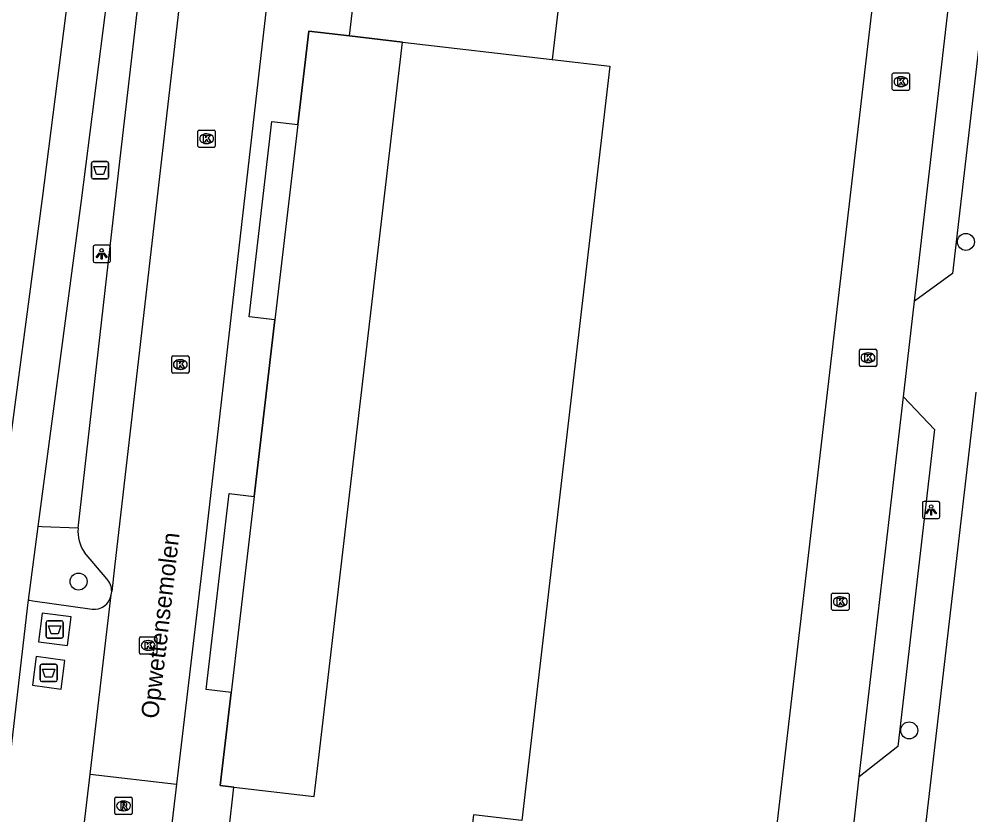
# Model space of a CAD drawing. Extents: x 161243 to 161752, y 384138 to 384885.
# Drawn here: x 161298.5 to 161353.3, y 384518.6 to 384564.5 of the extents above; entities that cross this region are included whole.
import ezdxf

# ---------------------------------------------------------------- set-up
doc = ezdxf.new("R2010")
doc.units = 0
for name, color, linetype in [('IMGEO_Afval_apart_plaats', 7, 'Continuous'), ('IMGEO_Afvalbak', 7, 'Continuous'), ('IMGEO_Berm_groen', 7, 'Continuous'), ('IMGEO_Boom', 7, 'Continuous'), ('IMGEO_Fietspad_gesloten', 7, 'Continuous'), ('IMGEO_Kolk', 7, 'Continuous'), ('IMGEO_Lichtpunt', 7, 'Continuous'), ('IMGEO_Openbare_ruimte_label', 7, 'Continuous'), ('IMGEO_Pand', 7, 'Continuous'), ('IMGEO_Pand_overbouw', 7, 'Continuous'), ('IMGEO_Parkeervlak_open', 7, 'Continuous'), ('IMGEO_Rijbaan_lokaal_open', 7, 'Continuous'), ('IMGEO_Rioolput', 7, 'Continuous'), ('IMGEO_Voetpad_gesloten', 7, 'Continuous'), ('IMGEO_Voetpad_open', 7, 'Continuous')]:
    doc.layers.add(name, color=color, linetype=linetype)

msp = doc.modelspace()

# ---------------------------------------------------------------- linework, layer by layer
at = {"layer": 'IMGEO_Afval_apart_plaats'}
for p, q in [((161300.128, 384529.767), (161300.918, 384529.767)), ((161300.918, 384529.767), (161300.128, 384529.767)), ((161300.028, 384528.867), (161300.028, 384529.667)), ((161300.028, 384529.667), (161300.028, 384528.867)), ((161301.018, 384529.667), (161301.018, 384528.867)), ((161301.018, 384528.867), (161301.018, 384529.667)), ((161300.918, 384528.767), (161300.128, 384528.767)), ((161300.128, 384528.767), (161300.918, 384528.767)), ((161299.68, 384526.363), (161299.68, 384527.163)), ((161299.68, 384527.163), (161299.68, 384526.363)), ((161299.78, 384527.263), (161300.57, 384527.263)), ((161300.57, 384527.263), (161299.78, 384527.263)), ((161300.67, 384527.163), (161300.67, 384526.363)), ((161300.67, 384526.363), (161300.67, 384527.163)), ((161300.57, 384526.263), (161299.78, 384526.263)), ((161299.78, 384526.263), (161300.57, 384526.263))]:
    msp.add_line(p, q, dxfattribs=at)
for points in [[(161300.171, 384529.481), (161300.875, 384529.481), (161300.726, 384529.011), (161300.32, 384529.011), (161300.171, 384529.481)], [(161299.823, 384526.977), (161300.527, 384526.977), (161300.378, 384526.507), (161299.972, 384526.507), (161299.823, 384526.977)]]:
    msp.add_lwpolyline(points, dxfattribs=at)
for centre, start, end in [((161300.128, 384529.667), 90, 180), ((161300.128, 384529.667), 90, 180), ((161300.918, 384529.667), 0, 90), ((161300.918, 384529.667), 360, 90), ((161300.128, 384528.867), 180, 270), ((161300.128, 384528.867), 180, 270), ((161300.918, 384528.867), 270, 0), ((161300.918, 384528.867), 270, 0), ((161299.78, 384527.163), 90, 180), ((161299.78, 384527.163), 90, 180), ((161300.57, 384527.163), 0, 90), ((161300.57, 384527.163), 360, 90), ((161299.78, 384526.363), 180, 270), ((161299.78, 384526.363), 180, 270), ((161300.57, 384526.363), 270, 0), ((161300.57, 384526.363), 270, 0)]:
    msp.add_arc(centre, 0.1, start, end, dxfattribs=at)
at = {"layer": 'IMGEO_Afvalbak'}
for p, q in [((161302.637, 384555.341), (161302.637, 384556.141)), ((161302.637, 384556.141), (161302.637, 384555.341)), ((161302.737, 384556.241), (161303.527, 384556.241)), ((161303.527, 384556.241), (161302.737, 384556.241)), ((161303.627, 384556.141), (161303.627, 384555.341)), ((161303.627, 384555.341), (161303.627, 384556.141)), ((161303.527, 384555.241), (161302.737, 384555.241)), ((161302.737, 384555.241), (161303.527, 384555.241))]:
    msp.add_line(p, q, dxfattribs=at)
msp.add_lwpolyline([(161302.78, 384555.955), (161303.484, 384555.955), (161303.335, 384555.485), (161302.929, 384555.485), (161302.78, 384555.955)], dxfattribs=at)
for centre, start, end in [((161302.737, 384556.141), 90, 180), ((161302.737, 384556.141), 90, 180), ((161303.527, 384556.141), 0, 90), ((161303.527, 384556.141), 360, 90), ((161302.737, 384555.341), 180, 270), ((161302.737, 384555.341), 180, 270), ((161303.527, 384555.341), 270, 0), ((161303.527, 384555.341), 270, 0)]:
    msp.add_arc(centre, 0.1, start, end, dxfattribs=at)
at = {"layer": 'IMGEO_Berm_groen'}
msp.add_lwpolyline([(161301.866, 384535.1), (161299.776, 384535.191), (161299.549, 384535.196)], dxfattribs=at)
at = {"layer": 'IMGEO_Boom'}
for centre in [(161353.058, 384551.609), (161301.899, 384532.026), (161349.789, 384523.448)]:
    msp.add_circle(centre, 0.489, dxfattribs=at)
at = {"layer": 'IMGEO_Fietspad_gesloten'}
msp.add_lwpolyline([(161270.005, 384301.578), (161270.134, 384303.063), (161273.019, 384327.449), (161276.269, 384355.259), (161281.811, 384402.692), (161289.671, 384470.352), (161296.755, 384531.182), (161299.82, 384554.106), (161304.483, 384590.763), (161310.58, 384642.356), (161311.044, 384646.284), (161311.712, 384651.942), (161311.774, 384652.424)], dxfattribs=at)
at = {"layer": 'IMGEO_Kolk'}
for p, q in [((161348.812, 384560.42), (161348.812, 384561.272)), ((161348.887, 384561.346), (161349.739, 384561.346)), ((161349.3, 384561.126), (161349.325, 384561.126)), ((161349.813, 384561.272), (161349.813, 384560.42)), ((161349.323, 384560.566), (161349.298, 384560.566)), ((161349.739, 384560.346), (161348.887, 384560.346)), ((161308.781, 384557.133), (161308.781, 384557.985)), ((161308.856, 384558.059), (161309.708, 384558.059)), ((161309.269, 384557.839), (161309.294, 384557.839)), ((161309.782, 384557.985), (161309.782, 384557.133)), ((161309.292, 384557.279), (161309.267, 384557.279)), ((161309.708, 384557.059), (161308.856, 384557.059)), ((161346.913, 384544.502), (161346.913, 384545.354)), ((161346.988, 384545.428), (161347.84, 384545.428)), ((161347.401, 384545.208), (161347.426, 384545.208)), ((161347.914, 384545.354), (161347.914, 384544.502)), ((161307.265, 384544.112), (161307.265, 384544.964)), ((161307.34, 384545.038), (161308.192, 384545.038)), ((161307.753, 384544.818), (161307.778, 384544.818)), ((161308.266, 384544.964), (161308.266, 384544.112)), ((161347.424, 384544.648), (161347.399, 384544.648)), ((161308.192, 384544.038), (161307.34, 384544.038)), ((161307.776, 384544.258), (161307.751, 384544.258)), ((161347.84, 384544.428), (161346.988, 384544.428)), ((161345.316, 384530.44), (161345.316, 384531.292)), ((161345.391, 384531.366), (161346.243, 384531.366)), ((161345.804, 384531.146), (161345.829, 384531.146)), ((161346.317, 384531.292), (161346.317, 384530.44)), ((161346.243, 384530.366), (161345.391, 384530.366)), ((161345.827, 384530.586), (161345.802, 384530.586)), ((161305.413, 384527.916), (161305.413, 384528.768)), ((161305.488, 384528.842), (161306.34, 384528.842)), ((161306.414, 384528.768), (161306.414, 384527.916)), ((161305.901, 384528.622), (161305.926, 384528.622)), ((161306.34, 384527.842), (161305.488, 384527.842)), ((161305.924, 384528.062), (161305.899, 384528.062))]:
    msp.add_line(p, q, dxfattribs=at)
for points in [[(161348.812, 384560.42), (161348.812, 384561.272)], [(161348.887, 384561.346), (161349.739, 384561.346)], [(161349.813, 384561.272), (161349.813, 384560.42)], [(161349.133, 384561.046), (161349.256, 384561.046), (161349.256, 384560.895), (161349.386, 384561.046), (161349.55, 384561.046), (161349.404, 384560.895), (161349.557, 384560.646), (161349.405, 384560.646), (161349.32, 384560.81), (161349.256, 384560.743), (161349.256, 384560.646), (161349.133, 384560.646), (161349.133, 384561.046)], [(161349.739, 384560.346), (161348.887, 384560.346)], [(161308.781, 384557.133), (161308.781, 384557.985)], [(161308.856, 384558.059), (161309.708, 384558.059)], [(161309.102, 384557.759), (161309.225, 384557.759), (161309.225, 384557.608), (161309.355, 384557.759), (161309.519, 384557.759), (161309.373, 384557.608), (161309.526, 384557.359), (161309.374, 384557.359), (161309.289, 384557.523), (161309.225, 384557.456), (161309.225, 384557.359), (161309.102, 384557.359), (161309.102, 384557.759)], [(161309.782, 384557.985), (161309.782, 384557.133)], [(161309.708, 384557.059), (161308.856, 384557.059)], [(161346.913, 384544.502), (161346.913, 384545.354)], [(161346.988, 384545.428), (161347.84, 384545.428)], [(161347.914, 384545.354), (161347.914, 384544.502)], [(161307.265, 384544.112), (161307.265, 384544.964)], [(161307.34, 384545.038), (161308.192, 384545.038)], [(161307.586, 384544.738), (161307.709, 384544.738), (161307.709, 384544.587), (161307.839, 384544.738), (161308.003, 384544.738), (161307.857, 384544.587), (161308.01, 384544.338), (161307.858, 384544.338), (161307.773, 384544.502), (161307.709, 384544.435), (161307.709, 384544.338), (161307.586, 384544.338), (161307.586, 384544.738)], [(161308.266, 384544.964), (161308.266, 384544.112)], [(161347.234, 384545.128), (161347.357, 384545.128), (161347.357, 384544.977), (161347.487, 384545.128), (161347.651, 384545.128), (161347.505, 384544.977), (161347.658, 384544.728), (161347.506, 384544.728), (161347.421, 384544.892), (161347.357, 384544.825), (161347.357, 384544.728), (161347.234, 384544.728), (161347.234, 384545.128)], [(161308.192, 384544.038), (161307.34, 384544.038)], [(161347.84, 384544.428), (161346.988, 384544.428)], [(161345.316, 384530.44), (161345.316, 384531.292)], [(161345.391, 384531.366), (161346.243, 384531.366)], [(161345.637, 384531.066), (161345.76, 384531.066), (161345.76, 384530.915), (161345.89, 384531.066), (161346.054, 384531.066), (161345.908, 384530.915), (161346.061, 384530.666), (161345.909, 384530.666), (161345.824, 384530.83), (161345.76, 384530.763), (161345.76, 384530.666), (161345.637, 384530.666), (161345.637, 384531.066)], [(161346.317, 384531.292), (161346.317, 384530.44)], [(161346.243, 384530.366), (161345.391, 384530.366)], [(161305.413, 384527.916), (161305.413, 384528.768)], [(161305.488, 384528.842), (161306.34, 384528.842)], [(161306.414, 384528.768), (161306.414, 384527.916)], [(161305.734, 384528.542), (161305.857, 384528.542), (161305.857, 384528.391), (161305.987, 384528.542), (161306.151, 384528.542), (161306.005, 384528.391), (161306.158, 384528.142), (161306.006, 384528.142), (161305.921, 384528.306), (161305.857, 384528.239), (161305.857, 384528.142), (161305.734, 384528.142), (161305.734, 384528.542)], [(161306.34, 384527.842), (161305.488, 384527.842)]]:
    msp.add_lwpolyline(points, dxfattribs=at)
for centre, start, end in [((161348.889, 384561.27), 91.552, 178.448), ((161348.889, 384561.27), 91.552, 178.448), ((161349.737, 384561.27), 1.552, 88.448), ((161349.737, 384561.27), 1.552, 88.448), ((161348.889, 384560.422), 181.552, 268.448), ((161348.889, 384560.422), 181.552, 268.448), ((161349.737, 384560.422), 271.552, 358.448), ((161349.737, 384560.422), 271.552, 358.448), ((161308.858, 384557.983), 91.552, 178.448), ((161308.858, 384557.983), 91.552, 178.448), ((161309.706, 384557.983), 1.552, 88.448), ((161309.706, 384557.983), 1.552, 88.448), ((161308.858, 384557.135), 181.552, 268.448), ((161308.858, 384557.135), 181.552, 268.448), ((161309.706, 384557.135), 271.552, 358.448), ((161309.706, 384557.135), 271.552, 358.448), ((161346.99, 384545.352), 91.552, 178.448), ((161346.99, 384545.352), 91.552, 178.448), ((161347.838, 384545.352), 1.552, 88.448), ((161347.838, 384545.352), 1.552, 88.448), ((161307.342, 384544.962), 91.552, 178.448), ((161307.342, 384544.962), 91.552, 178.448), ((161308.19, 384544.962), 1.552, 88.448), ((161308.19, 384544.962), 1.552, 88.448), ((161307.342, 384544.114), 181.552, 268.448), ((161307.342, 384544.114), 181.552, 268.448), ((161308.19, 384544.114), 271.552, 358.448), ((161308.19, 384544.114), 271.552, 358.448), ((161346.99, 384544.504), 181.552, 268.448), ((161346.99, 384544.504), 181.552, 268.448), ((161347.838, 384544.504), 271.552, 358.448), ((161347.838, 384544.504), 271.552, 358.448), ((161345.393, 384531.29), 91.552, 178.448), ((161345.393, 384531.29), 91.552, 178.448), ((161346.241, 384531.29), 1.552, 88.448), ((161346.241, 384531.29), 1.552, 88.448), ((161345.393, 384530.442), 181.552, 268.448), ((161345.393, 384530.442), 181.552, 268.448), ((161346.241, 384530.442), 271.552, 358.448), ((161346.241, 384530.442), 271.552, 358.448), ((161305.49, 384528.766), 91.552, 178.448), ((161305.49, 384528.766), 91.552, 178.448), ((161306.338, 384528.766), 1.552, 88.448), ((161306.338, 384528.766), 1.552, 88.448), ((161305.49, 384527.918), 181.552, 268.448), ((161305.49, 384527.918), 181.552, 268.448), ((161306.338, 384527.918), 271.552, 358.448), ((161306.338, 384527.918), 271.552, 358.448)]:
    msp.add_arc(centre, 0.0765, start, end, dxfattribs=at)
for centre, major_axis, ratio, start_param, end_param in [((161349.299, 384560.846), (-0.387, 0.002), 0.722429, 4.712389, 7.853982), ((161349.324, 384560.846), (-0.39, 0.002), 0.717154, 1.570796, 4.712389), ((161309.268, 384557.559), (-0.387, 0.002), 0.722429, 4.712389, 7.853982), ((161309.293, 384557.559), (-0.39, 0.002), 0.717154, 1.570796, 4.712389), ((161347.4, 384544.928), (-0.387, 0.002), 0.722429, 4.712389, 7.853982), ((161347.425, 384544.928), (-0.39, 0.002), 0.717154, 1.570796, 4.712389), ((161307.752, 384544.538), (-0.387, 0.002), 0.722429, 4.712389, 7.853982), ((161307.777, 384544.538), (-0.39, 0.002), 0.717154, 1.570796, 4.712389), ((161345.803, 384530.866), (-0.387, 0.002), 0.722429, 4.712389, 7.853982), ((161345.828, 384530.866), (-0.39, 0.002), 0.717154, 1.570796, 4.712389), ((161305.9, 384528.342), (-0.387, 0.002), 0.722429, 4.712389, 7.853982), ((161305.925, 384528.342), (-0.39, 0.002), 0.717154, 1.570796, 4.712389)]:
    msp.add_ellipse(centre, major_axis=major_axis, ratio=ratio, start_param=start_param, end_param=end_param, dxfattribs=at)
at = {"layer": 'IMGEO_Lichtpunt'}
for p, q in [((161302.733, 384551.323), (161302.733, 384550.516)), ((161302.733, 384551.323), (161302.733, 384550.516)), ((161303.635, 384551.418), (161302.827, 384551.418)), ((161303.635, 384551.418), (161302.827, 384551.418)), ((161303.729, 384550.516), (161303.729, 384551.323)), ((161303.729, 384550.516), (161303.729, 384551.323)), ((161302.827, 384550.422), (161303.635, 384550.422)), ((161302.827, 384550.422), (161303.635, 384550.422)), ((161350.554, 384536.556), (161350.554, 384535.749)), ((161350.554, 384536.556), (161350.554, 384535.749)), ((161351.456, 384536.651), (161350.648, 384536.651)), ((161351.456, 384536.651), (161350.648, 384536.651)), ((161351.55, 384535.749), (161351.55, 384536.556)), ((161351.55, 384535.749), (161351.55, 384536.556)), ((161350.648, 384535.655), (161351.456, 384535.655)), ((161350.648, 384535.655), (161351.456, 384535.655))]:
    msp.add_line(p, q, dxfattribs=at)
for points in [[(161303.107, 384550.987), (161303.146, 384550.959), (161302.958, 384550.697), (161302.92, 384550.724), (161303.107, 384550.987)], [(161303.209, 384550.939), (161303.256, 384550.939), (161303.256, 384550.617), (161303.209, 384550.617), (161303.209, 384550.939)], [(161303.319, 384550.959), (161303.357, 384550.986), (161303.544, 384550.724), (161303.505, 384550.696), (161303.319, 384550.959)], [(161350.928, 384536.22), (161350.967, 384536.192), (161350.779, 384535.93), (161350.741, 384535.957), (161350.928, 384536.22)], [(161351.03, 384536.172), (161351.077, 384536.172), (161351.077, 384535.85), (161351.03, 384535.85), (161351.03, 384536.172)], [(161351.14, 384536.192), (161351.178, 384536.219), (161351.365, 384535.957), (161351.326, 384535.929), (161351.14, 384536.192)]]:
    msp.add_lwpolyline(points, dxfattribs=at)
for centre in [(161303.232, 384551.121), (161351.053, 384536.354)]:
    msp.add_circle(centre, 0.0994, dxfattribs=at)
for centre, start, end in [((161302.827, 384551.323), 90, 180), ((161302.827, 384551.323), 90, 180), ((161303.635, 384551.323), 0, 90), ((161303.635, 384551.323), 0, 90), ((161302.827, 384550.516), 180, 270), ((161302.827, 384550.516), 180, 270), ((161303.635, 384550.516), 270, 0), ((161303.635, 384550.516), 270, 360), ((161350.648, 384536.556), 90, 180), ((161350.648, 384536.556), 90, 180), ((161351.456, 384536.556), 0, 90), ((161351.456, 384536.556), 0, 90), ((161350.648, 384535.749), 180, 270), ((161350.648, 384535.749), 180, 270), ((161351.456, 384535.749), 270, 0), ((161351.456, 384535.749), 270, 360)]:
    msp.add_arc(centre, 0.0946, start, end, dxfattribs=at)
at = {"layer": 'IMGEO_Pand'}
for points in [[(161317.518, 384563.483), (161317.825, 384566.114), (161320.416, 384565.812), (161328.853, 384638.376), (161330.482, 384638.186)], [(161385.31, 384636.318), (161384.492, 384629.298), (161341.346, 384634.326), (161341.28, 384633.76), (161338.47, 384631.536), (161337.879, 384631.605), (161330.356, 384566.963), (161329.778, 384567.03), (161329.206, 384562.128)], [(161317.518, 384563.483), (161320.568, 384563.129)], [(161310.857, 384520.181), (161315.485, 384519.641), (161315.768, 384522.059), (161320.568, 384563.129)], [(161320.568, 384563.129), (161329.206, 384562.128)], [(161329.206, 384562.128), (161332.52, 384561.741), (161327.448, 384518.254), (161324.658, 384518.579), (161324.09, 384513.711), (161326.898, 384513.383), (161325.337, 384500), (161321.817, 384469.82), (161318.472, 384470.21)], [(161309.469, 384514.874), (161307.919, 384515.054), (161307.974, 384515.528), (161308.245, 384517.862), (161310.556, 384517.594), (161310.857, 384520.181)]]:
    msp.add_lwpolyline(points, dxfattribs=at)
at = {"layer": 'IMGEO_Pand_overbouw'}
msp.add_lwpolyline([(161320.568, 384563.129), (161317.518, 384563.483), (161315.165, 384563.757), (161314.534, 384558.375), (161313.215, 384547.115), (161312.021, 384536.928), (161310.697, 384525.632), (161310.069, 384520.273), (161310.857, 384520.181), (161315.485, 384519.641), (161315.768, 384522.059)], close=True, dxfattribs=at)
at = {"layer": 'IMGEO_Parkeervlak_open'}
for points in [[(161301.866, 384535.1), (161304.293, 384556.423), (161305.574, 384567.529)], [(161303.525, 384532.183), (161302.238, 384533.704)], [(161298.986, 384530.962), (161299.086, 384530.946), (161299.265, 384530.92), (161302.672, 384530.431)]]:
    msp.add_lwpolyline(points, dxfattribs=at)
for centre, radius, start, end in [((161304.006, 384534.923), 2.147, 175.2616, 214.5808), ((161302.796, 384531.482), 1.012, 358.2094, 43.8761), ((161302.782, 384531.445), 1.02, 263.834, 349.0929)]:
    msp.add_arc(centre, radius, start, end, dxfattribs=at)
at = {"layer": 'IMGEO_Rijbaan_lokaal_open'}
for points in [[(161331.082, 384642.543), (161326.899, 384639.121), (161324.303, 384616.759), (161323.425, 384609.052), (161321.313, 384590.613), (161319.366, 384573.967), (161313.194, 384569.245), (161309.149, 384533.964), (161307.548, 384520.344)], [(161349.943, 384584.816), (161340.82, 384506.489)], [(161308.464, 384571.907), (161303.973, 384532.865), (161303.807, 384531.45)], [(161350.099, 384548.19), (161352.715, 384570.865)], [(161349.456, 384542.683), (161350.099, 384548.19)], [(161346.902, 384520.776), (161349.456, 384542.683)], [(161303.783, 384531.252), (161303.807, 384531.45)], [(161302.57, 384520.925), (161303.783, 384531.252)], [(161302.017, 384516.22), (161302.57, 384520.925)], [(161302.57, 384520.925), (161307.548, 384520.344)], [(161346.307, 384515.385), (161346.902, 384520.776)], [(161307.548, 384520.344), (161306.995, 384515.642)]]:
    msp.add_lwpolyline(points, dxfattribs=at)
at = {"layer": 'IMGEO_Rioolput'}
for p, q in [((161303.993, 384518.666), (161303.993, 384519.518)), ((161304.068, 384519.592), (161304.92, 384519.592)), ((161304.481, 384519.372), (161304.506, 384519.372)), ((161304.994, 384519.518), (161304.994, 384518.666)), ((161304.504, 384518.812), (161304.479, 384518.812)), ((161304.92, 384518.592), (161304.068, 384518.592))]:
    msp.add_line(p, q, dxfattribs=at)
for points in [[(161303.993, 384518.666), (161303.993, 384519.518)], [(161304.068, 384519.592), (161304.92, 384519.592)], [(161304.994, 384519.518), (161304.994, 384518.666)], [(161304.582, 384519.29), (161304.33, 384519.292), (161304.33, 384518.892)], [(161304.33, 384518.892), (161304.454, 384518.892), (161304.454, 384519.054), (161304.465, 384519.054)], [(161304.508, 384519.211), (161304.454, 384519.211), (161304.454, 384519.13)], [(161304.454, 384519.13), (161304.506, 384519.13)], [(161304.512, 384519.025), (161304.583, 384518.892), (161304.723, 384518.892), (161304.658, 384519.018)], [(161304.92, 384518.592), (161304.068, 384518.592)]]:
    msp.add_lwpolyline(points, dxfattribs=at)
for centre, radius, start, end in [((161304.07, 384519.516), 0.0765, 91.552, 178.448), ((161304.07, 384519.516), 0.0765, 91.552, 178.448), ((161304.918, 384519.516), 0.0765, 1.552, 88.448), ((161304.918, 384519.516), 0.0765, 1.552, 88.448), ((161304.464, 384519.001), 0.0533, 26.0293, 88.6989), ((161304.49, 384519.319), 0.19, 274.7715, 282.9687), ((161304.514, 384519.115), 0.0964, 77.0061, 93.1865), ((161304.528, 384519.172), 0.0378, 276.6634, 79.6772), ((161304.581, 384519.18), 0.109, 350.3612, 89.416), ((161304.579, 384519.18), 0.112, 277.5842, 350.9817), ((161304.563, 384518.965), 0.108, 29.5134, 73.7905), ((161304.07, 384518.668), 0.0765, 181.552, 268.448), ((161304.07, 384518.668), 0.0765, 181.552, 268.448), ((161304.918, 384518.668), 0.0765, 271.552, 358.448), ((161304.918, 384518.668), 0.0765, 271.552, 358.448)]:
    msp.add_arc(centre, radius, start, end, dxfattribs=at)
for centre, major_axis, ratio, start_param, end_param in [((161304.48, 384519.092), (-0.387, 0.002), 0.722429, 4.712389, 7.853982), ((161304.505, 384519.092), (-0.39, 0.002), 0.717154, 1.570796, 4.712389)]:
    msp.add_ellipse(centre, major_axis=major_axis, ratio=ratio, start_param=start_param, end_param=end_param, dxfattribs=at)
at = {"layer": 'IMGEO_Voetpad_gesloten'}
for points in [[(161301.465, 384529.988), (161299.793, 384530.202), (161299.582, 384528.546), (161301.254, 384528.333), (161301.465, 384529.988)], [(161301.113, 384527.474), (161299.458, 384527.698), (161299.236, 384526.051), (161300.891, 384525.828), (161301.113, 384527.474)]]:
    msp.add_lwpolyline(points, dxfattribs=at)
at = {"layer": 'IMGEO_Voetpad_open'}
for points in [[(161352.715, 384570.865), (161352.928, 384570.84), (161354.523, 384569.051), (161352.281, 384549.796), (161350.099, 384548.19)], [(161303.794, 384567.742), (161302.052, 384554.002), (161299.549, 384535.196)], [(161314.534, 384558.375), (161315.165, 384563.757), (161317.518, 384563.483)], [(161313.215, 384547.115), (161311.735, 384547.289), (161313.048, 384558.548), (161314.534, 384558.375)], [(161314.534, 384558.375), (161313.215, 384547.115)], [(161312.021, 384536.928), (161313.215, 384547.115)], [(161349.844, 384510.209), (161353.642, 384542.948)], [(161349.456, 384542.683), (161351.24, 384540.794), (161349.128, 384522.508), (161346.902, 384520.776)], [(161310.697, 384525.632), (161309.26, 384525.799), (161310.578, 384537.096), (161312.021, 384536.928)], [(161312.021, 384536.928), (161310.697, 384525.632)], [(161299.549, 384535.196), (161298.986, 384530.962)], [(161298.986, 384530.962), (161298.968, 384530.827), (161291.483, 384466.168)], [(161310.857, 384520.181), (161310.069, 384520.273), (161310.697, 384525.632)]]:
    msp.add_lwpolyline(points, dxfattribs=at)

# ---------------------------------------------------------------- texts
at = {"layer": 'IMGEO_Openbare_ruimte_label'}
msp.add_text('Opwettensemolen', height=1, rotation=83.394, dxfattribs=at).set_placement((161306.483, 384524.09))

doc.saveas('drawing.dxf')
